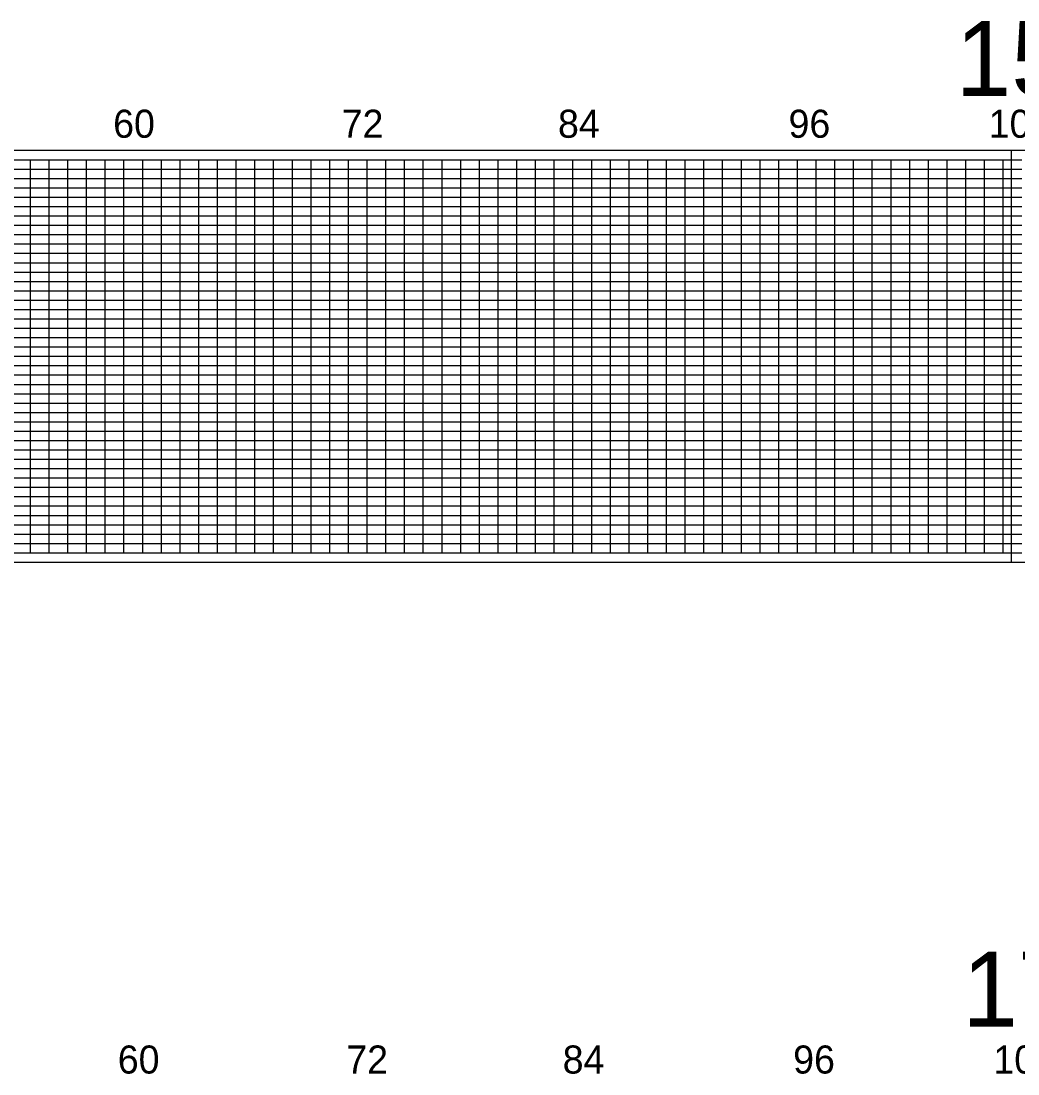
# Model space of a CAD drawing. Extents: x 1914168 to 1925341, y 720939 to 777401.
# Drawn here: x 1917167 to 1919832, y 739572 to 742385 of the extents above; entities that cross this region are included whole.
import ezdxf

# ---------------------------------------------------------------- set-up
doc = ezdxf.new("R2010")
doc.units = 0
for name, color, linetype in [('RD_PD_ALT1_CL', 7, 'Continuous'), ('RD_PD_WallFill', 7, 'Continuous'), ('RD_SHT_IplotShp', 7, 'Continuous')]:
    doc.layers.add(name, color=color, linetype=linetype)

msp = doc.modelspace()

# ---------------------------------------------------------------- linework, layer by layer
at = {"layer": 'RD_PD_WallFill'}
for p, q in [((1914492.5, 742014.1), (1919842.5, 742014.2)), ((1917192.5, 740964.2), (1917192.5, 742014.2)), ((1917242.5, 740964.2), (1917242.5, 742014.2)), ((1917292.5, 740964.2), (1917292.5, 742014.2)), ((1917342.5, 740964.2), (1917342.5, 742014.2)), ((1917392.5, 740964.2), (1917392.5, 742014.2)), ((1917442.5, 740964.2), (1917442.5, 742014.2)), ((1917492.5, 740964.2), (1917492.5, 742014.2)), ((1917542.5, 740964.2), (1917542.5, 742014.2)), ((1917592.5, 740964.1), (1917592.5, 742014.2)), ((1917642.5, 740964.2), (1917642.5, 742014.2)), ((1917692.5, 740964.2), (1917692.5, 742014.2)), ((1917742.5, 740964.2), (1917742.5, 742014.2)), ((1917792.5, 740964.2), (1917792.5, 742014.2)), ((1917842.5, 740964.2), (1917842.5, 742014.2)), ((1917892.5, 740964.1), (1917892.5, 742014.2)), ((1917942.5, 740964.1), (1917942.5, 742014.2)), ((1917992.5, 740964.2), (1917992.5, 742014.2)), ((1918042.5, 740964.2), (1918042.5, 742014.2)), ((1918092.5, 740964.2), (1918092.5, 742014.2)), ((1918142.5, 740964.2), (1918142.5, 742014.2)), ((1918192.5, 740964.2), (1918192.5, 742014.2)), ((1918242.5, 740964.2), (1918242.5, 742014.2)), ((1918292.5, 740964.2), (1918292.5, 742014.2)), ((1918342.5, 740964.2), (1918342.5, 742014.2)), ((1918392.5, 740964.2), (1918392.5, 742014.2)), ((1918442.5, 740964.2), (1918442.5, 742014.2)), ((1918492.5, 740964.2), (1918492.5, 742014.2)), ((1918542.5, 740964.2), (1918542.5, 742014.2)), ((1918592.5, 740964.2), (1918592.5, 742014.2)), ((1918642.5, 740964.2), (1918642.5, 742014.2)), ((1918692.5, 740964.2), (1918692.5, 742014.2)), ((1918742.5, 740964.2), (1918742.5, 742014.2)), ((1918792.5, 740964.2), (1918792.5, 742014.2)), ((1918842.5, 740964.2), (1918842.5, 742014.2)), ((1918892.5, 740964.2), (1918892.5, 742014.2)), ((1918942.5, 740964.2), (1918942.5, 742014.2)), ((1918992.5, 740964.2), (1918992.5, 742014.2)), ((1919042.5, 740964.2), (1919042.5, 742014.2)), ((1919092.5, 740964.2), (1919092.5, 742014.2)), ((1919142.5, 740964.2), (1919142.5, 742014.2)), ((1919192.5, 740964.2), (1919192.5, 742014.2)), ((1919242.5, 740964.2), (1919242.5, 742014.2)), ((1919292.5, 740964.2), (1919292.5, 742014.2)), ((1919342.5, 740964.2), (1919342.5, 742014.2)), ((1919392.5, 740964.2), (1919392.5, 742014.2)), ((1919442.5, 740964.2), (1919442.5, 742014.2)), ((1919492.5, 740964.2), (1919492.5, 742014.2)), ((1919542.5, 740964.2), (1919542.5, 742014.2)), ((1919592.5, 740964.2), (1919592.5, 742014.2)), ((1919642.5, 740964.2), (1919642.5, 742014.2)), ((1919692.5, 740964.2), (1919692.5, 742014.2)), ((1919742.5, 740964.2), (1919742.5, 742014.2)), ((1919792.5, 740964.2), (1919792.5, 742014.2)), ((1914942.5, 741989.1), (1919842.5, 741989.1)), ((1914942.5, 741964.1), (1919842.5, 741964.1)), ((1914942.5, 741939.1), (1919842.5, 741939.1)), ((1914942.5, 741914.2), (1919842.5, 741914.1)), ((1914942.5, 741889.1), (1919842.5, 741889.2)), ((1914492.5, 741864.1), (1919842.5, 741864.1)), ((1914492.5, 741839.1), (1919842.5, 741839.1)), ((1914492.5, 741814.1), (1919842.5, 741814.2)), ((1914492.5, 741789.2), (1919842.5, 741789.1)), ((1914492.5, 741764.2), (1919842.5, 741764.2)), ((1914492.5, 741739.1), (1919842.5, 741739.1)), ((1914492.5, 741714.1), (1919842.5, 741714.1)), ((1914492.5, 741689.2), (1919842.5, 741689.1)), ((1914492.5, 741664.1), (1919842.5, 741664.1)), ((1914492.5, 741639.2), (1919842.5, 741639.1)), ((1914492.5, 741614.1), (1919842.5, 741614.1)), ((1914492.5, 741589.1), (1919842.5, 741589.2)), ((1914492.5, 741564.1), (1919842.5, 741564.1)), ((1914492.5, 741539.1), (1919842.5, 741539.2)), ((1914492.5, 741514.1), (1919842.5, 741514.1)), ((1914492.5, 741489.1), (1919842.5, 741489.1)), ((1914492.5, 741464.2), (1919842.5, 741464.1)), ((1914492.5, 741439.1), (1919842.5, 741439.1)), ((1914492.5, 741414.1), (1919842.5, 741414.1)), ((1914492.5, 741389.1), (1919842.5, 741389.1)), ((1914492.5, 741364.1), (1919842.5, 741364.2)), ((1914492.5, 741339.1), (1919842.5, 741339.1)), ((1914492.5, 741314.1), (1919842.5, 741314.1)), ((1914492.5, 741289.1), (1919842.5, 741289.1)), ((1914492.5, 741264.1), (1919842.5, 741264.1)), ((1914492.5, 741239.1), (1919842.5, 741239.1)), ((1914492.5, 741214.1), (1919842.5, 741214.1)), ((1914492.5, 741189.1), (1919842.5, 741189.1)), ((1914492.5, 741164.1), (1919842.5, 741164.1)), ((1914492.5, 741139.1), (1919842.5, 741139.1)), ((1914492.5, 741114.1), (1919842.5, 741114.1)), ((1914492.5, 741089.1), (1919842.5, 741089.1)), ((1914492.5, 741064.1), (1919842.5, 741064.1)), ((1914492.5, 741039.1), (1919842.5, 741039.1)), ((1914492.5, 741014.1), (1919842.5, 741014.1)), ((1914542.5, 740989.1), (1919842.5, 740989.1)), ((1914492.5, 740964.1), (1919842.5, 740964.1))]:
    msp.add_line(p, q, dxfattribs=at)
at = {"layer": 'RD_SHT_IplotShp'}
for points in [[(1914467.5, 740939.1), (1919867.5, 740939.1), (1919867.5, 742039.1), (1914467.5, 742039.1)], [(1919813.4, 740939.1), (1925213.4, 740939.1), (1925213.4, 742039.1), (1919813.4, 742039.1)]]:
    msp.add_lwpolyline(points, close=True, dxfattribs=at)

# ---------------------------------------------------------------- texts
at = {"layer": 'RD_PD_ALT1_CL'}
for s, p in [('15', (1919665.3, 742184.6)), ('17', (1919682.8, 739698.5))]:
    msp.add_text(s, height=200, dxfattribs=at).set_placement(p)
at = {"layer": 'RD_PD_WallFill'}
for s, p in [('60', (1917413.6, 742072.8)), ('72', (1918024.3, 742072.8)), ('84', (1918602.5, 742072.8)), ('96', (1919218.6, 742072.8)), ('108', (1919753.6, 742072.8)), ('60', (1917426, 739572.8)), ('72', (1918036.7, 739572.8)), ('84', (1918615, 739572.8)), ('96', (1919231, 739572.8)), ('108', (1919766.1, 739572.8))]:
    msp.add_text(s, height=75, dxfattribs=at).set_placement(p)

doc.saveas('drawing.dxf')
